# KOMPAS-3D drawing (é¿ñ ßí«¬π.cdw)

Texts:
  ПЛК.303120.00.00 СБ
  Ревин ЕЕ
  Лит-Масса-Масштаб
  Материал-Предприятие
  ACAD_ISO10W100_RGB_255_128_0_SC_1_THICK_0.15
  ACAD_ISO10W100_RGB_51_51_51_SC_1_THICK_0.15
  ACAD_ISO10W100_RGB_255_128_0_SC_0.5_THICK_0.15
  ACAD_ISO10W100_RGB_255_64_0_SC_1_THICK_0.15
  ACAD_ISO08W100_RGB_255_64_0_SC_1_THICK_0.15
  ACAD_ISO03W100_RGB_0_0_0_SC_0.3_THICK_0.15
  ACAD_ISO10W100_RGB_255_63_0_SC_1_THICK_0.15
  ACAD_ISO10W100_RGB_255_63_0_SC_0.25_THICK_0.15
  ACAD_ISO10W100_RGB_255_63_0_SC_0.5_THICK_0.15
  gost6_RGB_255_128_0_SC_1_THICK_0.15
  ACAD_ISO10W100_RGB_51_51_51_SC_1_THICK_0.18
  ACAD_ISO10W100_RGB_0_0_0_SC_1_THICK_0.18
  gost6_RGB_255_128_0_SC_0.5_THICK_0.15
  ACAD_ISO10W100_RGB_51_51_51_SC_0.1_THICK_0.25
  POLYLINE_STYLE_0.18_RGB_0_0_255
  ACAD_ISO10W100_RGB_255_128_0_SC_0.75_THICK_0.15
  ACAD_ISO03W100_RGB_0_0_255_SC_0.25_THICK_0.5
  ACAD_ISO03W100_RGB_0_0_0_SC_0.1_THICK_0.15
  ACAD_ISO10W100_RGB_255_128_0_SC_1_THICK_0.18
  ACAD_ISO10W100_RGB_51_51_51_SC_1_THICK_0.25
  ACAD_ISO10W100_RGB_0_0_255_SC_0.5_THICK_0.15
  СONTINUOUS_RGB_0_0_0_THICK_0.5
  ACAD_ISO10W100_RGB_255_128_0_SC_0.25_THICK_0.15
  ACAD_ISO10W100_RGB_255_64_0_SC_1_THICK_0.18
  Стили документа
  Подшипник 36207K ГОСТ 831-75
  Подшипник
  ГОСТ
  Подшипник 7212А ГОСТ 27365-87
  Подшипник207 ГОСТ 8338-75
  Подшипник209 ГОСТ 8338-75
  Манжета
  Шайба 8 Л БрКМц3-1 ГОСТ 6402-70
  Шайба пружинная
  Шайба
  БрКМц3-1
  БрКМц3-1 ГОСТ 18175-78
  Болт М8-6g x 22.109.30ХГСА ГОСТ 7808-70
  Болт
  .30ХГСА
  Сталь 30ХГСА ГОСТ 4543-71
  ANSI37
  Редуктор цилиндрический
  двухступенчатый
  Сборочный чертеж
  Семенов А.М.
  РЦО.112.00.00 СБ-
  НИТПУ, ИДО,
  группа з-4681
Dimensions and other numbers on the sheet: 370; 415; 625; 130; 58; 70; 2; 55; 029; -6g; 1:1; 3; 0; 1; 4; 5; 6; 7; 8; 9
